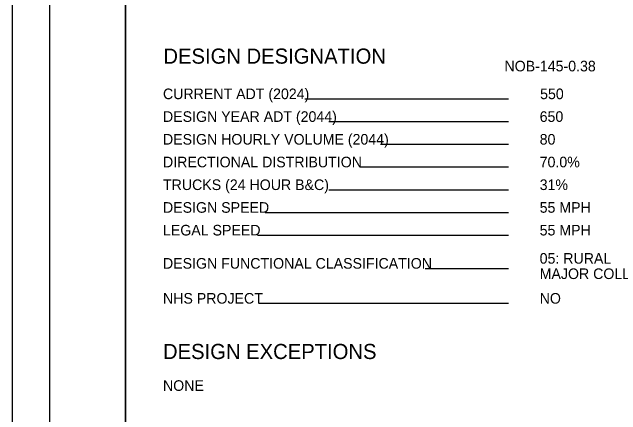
# Model space of a CAD drawing. Extents: x -10.5 to 40.6, y -3.2 to 22.
# Drawn here: x 0 to 8.05, y 5.64 to 10.95 of the extents above; entities that cross this region are included whole.
import ezdxf

# ---------------------------------------------------------------- set-up
doc = ezdxf.new("R2010")
doc.units = 0
for name, color, linetype in [('SH_Border', 7, 'Continuous'), ('SH_Cut_Line', 7, 'Continuous'), ('SH_Data', 7, 'Continuous'), ('SH_Text', 7, 'Continuous')]:
    doc.layers.add(name, color=color, linetype=linetype)

msp = doc.modelspace()

# ---------------------------------------------------------------- linework, layer by layer
at = {"layer": 'SH_Border'}
for points in [[(0.5, 21.5), (1.5, 21.5), (1.5, 0.5), (0.5, 0.5)], [(1.5, 21.5), (33.5, 21.5), (33.5, 0.5), (1.5, 0.5)]]:
    msp.add_lwpolyline(points, close=True, dxfattribs=at)
at = {"layer": 'SH_Cut_Line'}
msp.add_lwpolyline([(0, 0), (34, 0), (34, 22), (0, 22)], close=True, dxfattribs=at)
at = {"layer": 'SH_Data'}
for p, q in [((6.5642, 9.8062), (3.871, 9.8062)), ((6.5642, 9.5062), (4.1885, 9.5062)), ((6.5642, 9.2062), (4.8723, 9.2062)), ((6.5642, 8.9062), (4.6037, 8.9062)), ((6.5642, 8.6062), (4.1885, 8.6062)), ((6.5642, 8.3062), (3.346, 8.3062)), ((6.5642, 8.0062), (3.2422, 8.0062)), ((6.5642, 7.5679), (5.4633, 7.5679)), ((6.5642, 7.1062), (3.2669, 7.1062))]:
    msp.add_line(p, q, dxfattribs=at)

# ---------------------------------------------------------------- texts
for s, height, p in [('DESIGN DESIGNATION', 0.2, (2, 10.2747)), ('NOB-145-0.38', 0.14, (6.5105, 10.1731))]:
    msp.add_text(s, height=height, dxfattribs=at).set_placement(p)
at = {"layer": 'SH_Text'}
for s, height, p in [('CURRENT ADT (2024)', 0.14, (1.9944, 9.8062)), ('550', 0.14, (6.9815, 9.8062)), ('DESIGN YEAR ADT (2044)', 0.14, (1.9944, 9.5062)), ('650', 0.14, (6.9759, 9.5062)), ('DESIGN HOURLY VOLUME (2044)', 0.14, (1.9944, 9.2062)), ('80', 0.14, (6.9759, 9.2062)), ('DIRECTIONAL DISTRIBUTION', 0.14, (1.9944, 8.9062)), ('70.0%', 0.14, (6.9759, 8.9062)), ('TRUCKS (24 HOUR B&C)', 0.14, (1.9944, 8.6062)), ('31%', 0.14, (6.9759, 8.6062)), ('DESIGN SPEED', 0.14, (1.9944, 8.3062)), ('55 MPH', 0.14, (6.9759, 8.3062)), ('LEGAL SPEED', 0.14, (1.9944, 8.0062)), ('55 MPH', 0.14, (6.9759, 8.0062)), ('05: RURAL ', 0.14, (6.9759, 7.6337)), ('DESIGN FUNCTIONAL CLASSIFICATION', 0.14, (1.9944, 7.5679)), ('MAJOR COLLECTOR', 0.14, (6.9759, 7.4312)), ('NHS PROJECT', 0.14, (1.9944, 7.1062)), ('NO', 0.14, (6.9759, 7.1062)), ('DESIGN EXCEPTIONS', 0.2, (1.9944, 6.3744)), ('NONE', 0.14, (1.9944, 5.9544))]:
    msp.add_text(s, height=height, dxfattribs=at).set_placement(p)

doc.saveas('drawing.dxf')
